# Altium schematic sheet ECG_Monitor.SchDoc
size A; SheetNumber: 1; SheetTotal: 1
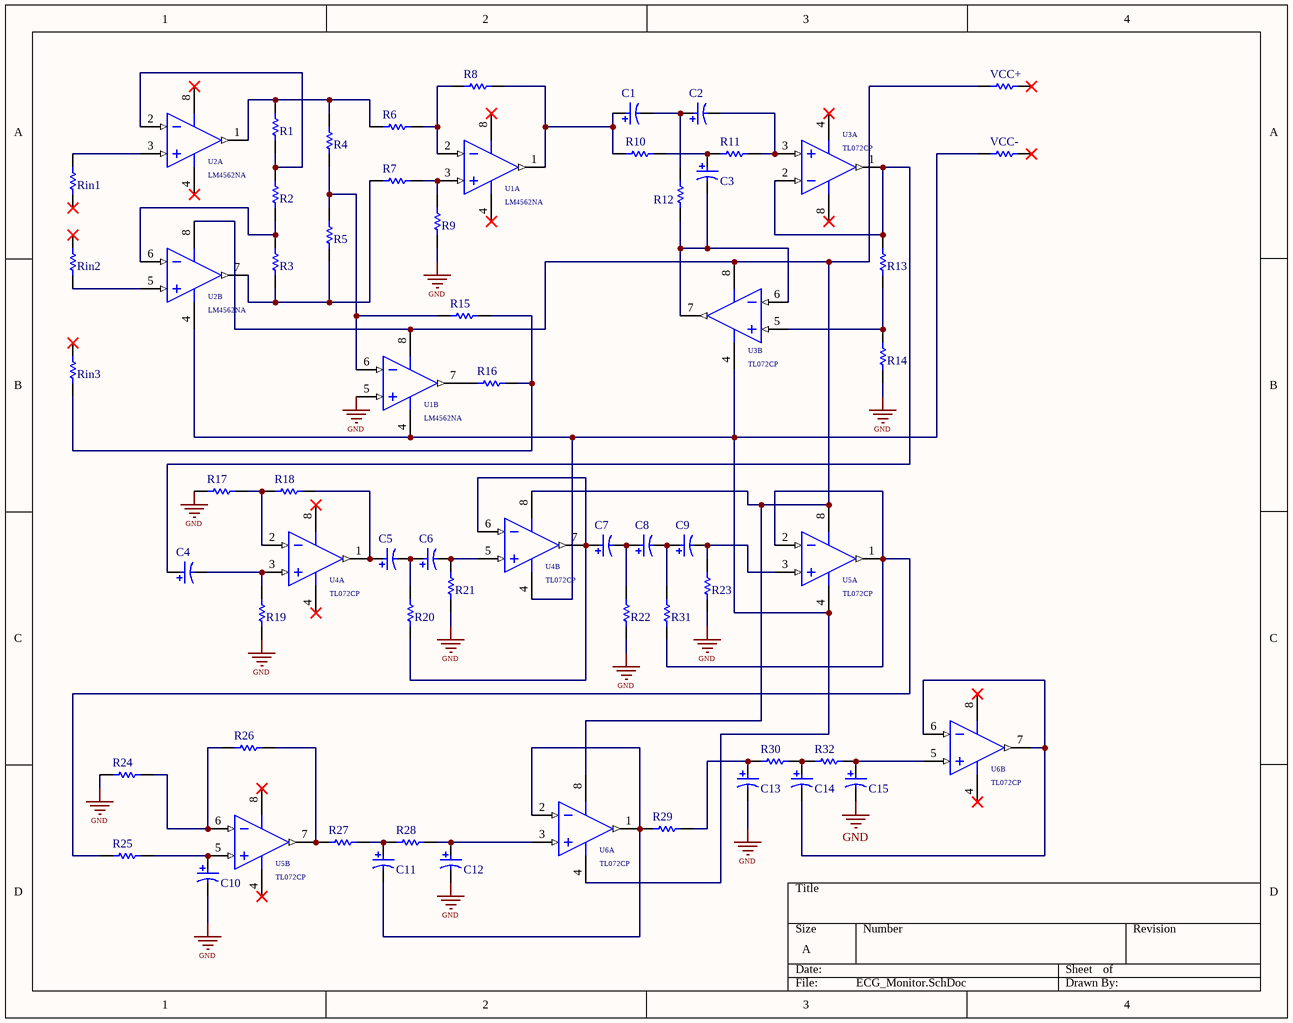
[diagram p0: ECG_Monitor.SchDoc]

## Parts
C1  ECA1HM100  [CAPPR55-200-1100X500X1200]  (value not drawn)
C2  ECA1HM100  [CAPPR55-200-1100X500X1200]  (value not drawn)
C3  ECA1HM100  [CAPPR55-200-1100X500X1200]  (value not drawn)
C4  ECA1HM100  [CAPPR55-200-1100X500X1200]  (value not drawn)
C5  ECA1HM100  [CAPPR55-200-1100X500X1200]  (value not drawn)
C6  ECA1HM100  [CAPPR55-200-1100X500X1200]  (value not drawn)
C7  ECA1HM100  [CAPPR55-200-1100X500X1200]  (value not drawn)
C8  ECA1HM100  [CAPPR55-200-1100X500X1200]  (value not drawn)
C9  ECA1HM100  [CAPPR55-200-1100X500X1200]  (value not drawn)
C10  ECA1HM100  [CAPPR55-200-1100X500X1200]  (value not drawn)
C11  ECA1HM100  [CAPPR55-200-1100X500X1200]  (value not drawn)
C12  ECA1HM100  [CAPPR55-200-1100X500X1200]  (value not drawn)
C13  ECA1HM100  [CAPPR55-200-1100X500X1200]  (value not drawn)
C14  ECA1HM100  [CAPPR55-200-1100X500X1200]  (value not drawn)
C15  ECA1HM100  [CAPPR55-200-1100X500X1200]  (value not drawn)
R1  (no value)  [RESA60-630X240]
R2  (no value)  [RESA60-630X240]
R3  (no value)  [RESA60-630X240]
R4  (no value)  [RESA60-630X240]
R5  (no value)  [RESA60-630X240]
R6  (no value)  [RESA60-630X240]
R7  (no value)  [RESA60-630X240]
R8  (no value)  [RESA60-630X240]
R9  (no value)  [RESA60-630X240]
R10  (no value)  [RESA60-630X240]
R11  (no value)  [RESA60-630X240]
R12  (no value)  [RESA60-630X240]
R13  (no value)  [RESA60-630X240]
R14  (no value)  [RESA60-630X240]
R15  (no value)  [RESA60-630X240]
R16  (no value)  [RESA60-630X240]
R17  (no value)  [RESA60-630X240]
R18  (no value)  [RESA60-630X240]
R19  (no value)  [RESA60-630X240]
R20  (no value)  [RESA60-630X240]
R21  (no value)  [RESA60-630X240]
R22  (no value)  [RESA60-630X240]
R23  (no value)  [RESA60-630X240]
R24  (no value)  [RESA60-630X240]
R25  (no value)  [RESA60-630X240]
R26  (no value)  [RESA60-630X240]
R27  (no value)  [RESA60-630X240]
R28  (no value)  [RESA60-630X240]
R29  (no value)  [RESA60-630X240]
R30  (no value)  [RESA60-630X240]
R31  (no value)  [RESA60-630X240]
R32  (no value)  [RESA60-630X240]
Rin1  (no value)  [RESA60-630X240]
Rin2  (no value)  [RESA60-630X240]
Rin3  (no value)  [RESA60-630X240]
U1  LM4562NA  [N08E]  (parts A,B of 2)
U2  LM4562NA  [N08E]  (parts A,B of 2)
U3  TL072CP  [P0008A]  (parts A,B of 2)
U4  TL072CP  [P0008A]  (parts A,B of 2)
U5  TL072CP  [P0008A]  (parts A,B of 2)
U6  TL072CP  [P0008A]  (parts A,B of 2)
VCC+  (no value)  [RESA60-630X240]
VCC-  (no value)  [RESA60-630X240]

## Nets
GND: C10.2 C12.2 C13.2 C15.2 R9.1 R14.1 R17.1 R19.1 R21.1 R22.1 R23.1 R24.1 U1.5(IN_B)
NetC1_1: C1.1 R8.2 R10.1 U1.1(OUT_A)
NetC1_2: C1.2 C2.1 R12.2
NetC2_2: C2.2 R11.2 U3.3(IN1+)
NetC3_1: C3.1 R10.2 R11.1
NetC3_2: C3.2 R12.1 U3.6(IN2-) U3.7(OUT2)
NetC4_1: C4.1 R13.2 U3.1(OUT1) U3.2(IN1-)
NetC4_2: C4.2 R19.2 U4.3(IN1+)
NetC5_1: C5.1 R18.2 U4.1(OUT1)
NetC5_2: C5.2 C6.1 R20.2
NetC6_2: C6.2 R21.2 U4.5(IN2+)
NetC7_1: C7.1 R20.1 U4.6(IN2-) U4.7(OUT2)
NetC7_2: C7.2 C8.1 R22.2
NetC8_2: C8.2 C9.1 R31.2
NetC9_2: C9.2 R23.2 U5.3(IN1+)
NetC10_1: C10.1 R25.2 U5.5(IN2+)
NetC11_1: C11.1 R27.2 R28.1
NetC11_2: C11.2 R29.1 U6.1(OUT1) U6.2(IN1-)
NetC12_1: C12.1 R28.2 U6.3(IN1+)
NetC13_1: C13.1 R29.2 R30.1
NetC14_1: C14.1 R30.2 R32.1
NetC14_2: C14.2 U6.6(IN2-) U6.7(OUT2)
NetC15_1: C15.1 R32.2 U6.5(IN2+)
NetR1_1: R1.1 R2.2 U2.2(IN_A)
NetR1_2: R1.2 R4.2 R6.1 U2.1(OUT_A)
NetR2_1: R2.1 R3.2 U2.6(IN_B)
NetR3_1: R3.1 R5.1 R7.1 U2.7(OUT_B)
NetR4_1: R4.1 R5.2 R15.1 U1.6(IN_B)
NetR6_2: R6.2 R8.1 U1.2(IN_A)
NetR7_2: R7.2 R9.2 U1.3(IN_A)
NetR13_1: R13.1 R14.2 U3.5(IN2+)
NetR15_2: R15.2 R16.2 Rin3.1
NetR16_1: R16.1 U1.7(OUT_B)
NetR17_2: R17.2 R18.1 U4.2(IN1-)
NetR24_2: R24.2 R26.1 U5.6(IN2-)
NetR25_1: R25.1 R31.1 U5.1(OUT1) U5.2(IN1-)
NetR26_2: R26.2 R27.1 U5.7(OUT2)
NetRin1_2: Rin1.2 U2.3(IN_A)
NetRin2_1: Rin2.1 U2.5(IN_B)
NetU1_4: U1.4(V-) U2.4(V-) U3.4(VCC-) U4.4(VCC-) U5.4(VCC-) U6.4(VCC-) VCC-.1
NetU1_8: U1.8(V+) U2.8(V+) U3.8(VCC+) U4.8(VCC+) U5.8(VCC+) U6.8(VCC+) VCC+.1

Not connected (* = marked no-connect by the designer): Rin1 1*; Rin2 2*; Rin3 2*; VCC+ 2*; VCC- 2*

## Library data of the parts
C1-C15 = CMP-1665-00038-2: Aluminum Electrolytic Capacitor, 10 uF, +/- 20%, 50 V, -40 to 85 degC, 2-Pin THD, RoHS, Bulk; Manufacturer: Panasonic; Life (Hours): 2000Hour; Lead/Base Style: Straight; Dissipation Factor: 0.12%; Capacitance: 10uF; Leakage Current: 3uA; Dielectric Material: Aluminium; Lead Diameter: 0.5mm; Voltage Rating: 50V; Ripple Current: 65mA
R1-R32 Rin1-Rin3 VCC+ VCC- = CMP-1659-00072-1: Axial Resistor, 221 Ohm, +/- 1%, 250 mW, -55 to 155 degC, 2-Pin THD, RoHS, Bulk; Max Supply Voltage: 3.6 V; Min Supply Voltage: 1.95 V; Interface: I2C; Case\Package: QFN; Nominal Supply Voltage: 2.5 V; Bandwidth: 800 Hz
U1 U2 = CMP-0057-00043-2: Dual High Performance, High Fidelity Audio Operational Amplifier, 8-pin MDIP; Manufacturer: National Semiconductor; PowerWise: Y; PackageTopMarking: NSUZXYTT*LM*4562NA; CompType: Audio IC
U3-U6 = CMP-0017-00950-2: Dual Low-Noise JFET-Input General-Purpose Operational Amplifier, 7 to 36 V, 0 to 70 degC, 8-pin DIP (P8), Pb-Free (RoHS); Manufacturer: Texas Instruments; Sub Family: General Purpose Amplifier, High Supply Voltage Amplifier (>=30V); Total Supply Voltage(Max)(+5V is 5, +/-5V is 10): 36; Slew Rate(Typ)(V/us): 13; Vn at 1kHz(Typ)(nV/rtHz): 18; GBW(Typ)(MHz): 3; CMRR(Min)(dB): 70; Total Supply Voltage(Min)(+5V is 5, +/-5V is 10): 7; Vio (25C)(Max)(mV): 10; Rating: Catalog; IIB(Max)(pA): 200; Iq per channel(Max)(mA): 2.5; Number of Channels: 2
